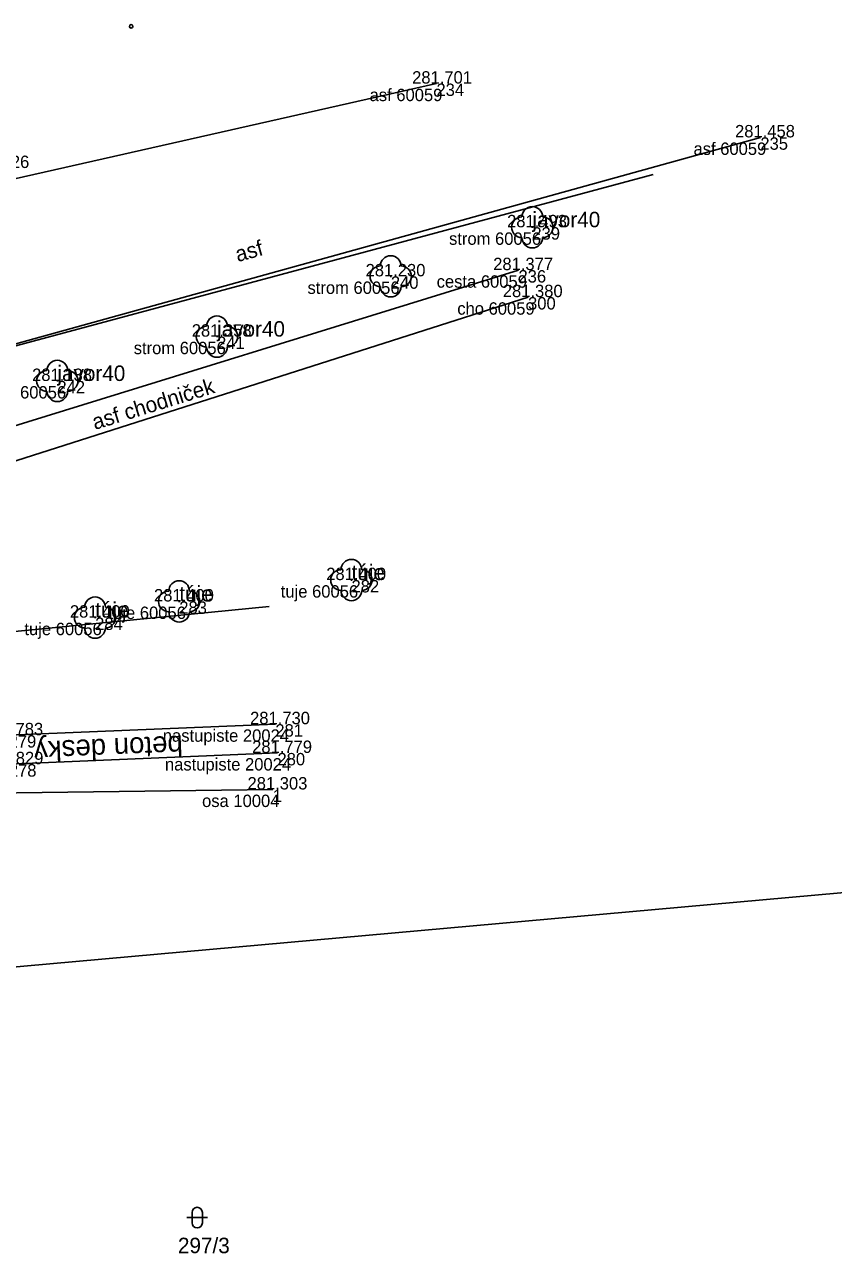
# Model space of a CAD drawing. Extents: x -728659 to -728362, y -1073110 to -1072943.
# Drawn here: x -728474.1 to -728435, y -1073066.8 to -1073007.2 of the extents above; entities that cross this region are included whole.
import ezdxf

# ---------------------------------------------------------------- set-up
doc = ezdxf.new("R2010")
doc.units = 0
for name, color, linetype in [('Vrstva 1', 7, 'Continuous'), ('Vrstva 14', 7, 'Continuous'), ('Vrstva 50', 7, 'Continuous'), ('Vrstva 51', 7, 'Continuous'), ('Vrstva 53', 7, 'Continuous'), ('Vrstva 55', 7, 'Continuous'), ('Vrstva 57', 7, 'Continuous'), ('Vrstva 58', 7, 'Continuous'), ('Vrstva 59', 7, 'Continuous'), ('Vrstva 60', 7, 'Continuous'), ('Vrstva 61', 7, 'Continuous'), ('Vrstva 62', 7, 'Continuous'), ('Vrstva 63', 7, 'Continuous')]:
    doc.layers.add(name, color=color, linetype=linetype)

msp = doc.modelspace()

# ---------------------------------------------------------------- linework, layer by layer
at = {"layer": 'Vrstva 1'}
msp.add_lwpolyline([(-728462.112, -1073044.292), (-728486.957, -1073044.611), (-728498.776, -1073043.699), (-728511.695, -1073041.857), (-728514.393, -1073041.361), (-728535.912, -1073035.983), (-728560.369, -1073026.548)], dxfattribs=at)
at = {"layer": 'Vrstva 14'}
msp.add_lwpolyline([(-728461.988, -1073041.13), (-728474.913, -1073041.665), (-728486.835, -1073041.479), (-728486.937, -1073042.858), (-728474.902, -1073043.068), (-728461.886, -1073042.523)], dxfattribs=at)
at = {"layer": 'Vrstva 50'}
for p, q in [((-728449.571, -1073017.062), (-728449.5, -1073017.062)), ((-728456.429, -1073019.439), (-728456.358, -1073019.439)), ((-728464.848, -1073022.358), (-728464.777, -1073022.358)), ((-728472.584, -1073024.506), (-728472.513, -1073024.506)), ((-728458.334, -1073034.149), (-728458.264, -1073034.149)), ((-728466.679, -1073035.184), (-728466.608, -1073035.184)), ((-728470.755, -1073035.967), (-728470.684, -1073035.967))]:
    msp.add_line(p, q, dxfattribs=at)
for centre, start, end in [((-728449.542, -1073016.561), 0, 180), ((-728450.042, -1073017.061), 90, 270), ((-728449.042, -1073017.061), 270, 90), ((-728449.542, -1073017.561), 180, 0), ((-728456.399, -1073018.938), 0, 180), ((-728456.899, -1073019.438), 90, 270), ((-728455.899, -1073019.438), 270, 90), ((-728456.399, -1073019.938), 180, 0), ((-728465.319, -1073022.357), 90, 270), ((-728464.819, -1073021.857), 0, 180), ((-728464.319, -1073022.357), 270, 90), ((-728464.819, -1073022.857), 180, 0), ((-728472.554, -1073024.005), 0, 180), ((-728473.054, -1073024.505), 90, 270), ((-728472.054, -1073024.505), 270, 90), ((-728472.554, -1073025.005), 180, 0), ((-728458.304, -1073033.648), 0, 180), ((-728458.804, -1073034.148), 90, 270), ((-728457.804, -1073034.148), 270, 90), ((-728466.65, -1073034.683), 0, 180), ((-728470.726, -1073035.466), 0, 180), ((-728467.15, -1073035.183), 90, 270), ((-728466.15, -1073035.183), 270, 90), ((-728458.304, -1073034.648), 180, 0), ((-728471.226, -1073035.966), 90, 270), ((-728470.226, -1073035.966), 270, 90), ((-728466.65, -1073035.683), 180, 0), ((-728470.726, -1073036.466), 180, 0)]:
    msp.add_arc(centre, 0.5, start, end, dxfattribs=at)
at = {"layer": 'Vrstva 51'}
for points in [[(-728494.628, -1073019.466), (-728481.269, -1073016.431), (-728476.07, -1073015.036), (-728454.183, -1073010.103)], [(-728491.401, -1073027.273), (-728490.555, -1073027.131), (-728438.49, -1073012.708)], [(-728491.25, -1073027.888), (-728489.777, -1073030.86), (-728476.655, -1073027.306), (-728450.209, -1073019.139)], [(-728449.745, -1073020.446), (-728480.35, -1073030.208), (-728490.255, -1073033.191), (-728496.482, -1073035.776)]]:
    msp.add_lwpolyline(points, dxfattribs=at)
at = {"layer": 'Vrstva 53'}
msp.add_lwpolyline([(-728443.68, -1073014.51), (-728493.68, -1073027.94), (-728497.54, -1073030.15), (-728499.78, -1073032.61), (-728501.19, -1073037.94), (-728503.24, -1073052.34), (-728496.81, -1073052.21), (-728491.97, -1073053.44), (-728477.97, -1073053.19), (-728434.587, -1073049.291), (-728361.73, -1073039.5)], dxfattribs=at)
at = {"layer": 'Vrstva 55'}
msp.add_lwpolyline([(-728462.29, -1073035.43), (-728488.6, -1073038.02), (-728488.39, -1073034.38), (-728493.51, -1073034.35), (-728493.84, -1073039.37), (-728501.19, -1073037.94)], dxfattribs=at)
at = {"layer": 'Vrstva 58'}
for p, q in [((-728466.277, -1073065.028), (-728465.277, -1073065.028)), ((-728466.027, -1073064.778), (-728466.027, -1073065.278)), ((-728465.527, -1073064.778), (-728465.527, -1073065.278))]:
    msp.add_line(p, q, dxfattribs=at)
for centre, start, end in [((-728465.777, -1073064.778), 0, 180), ((-728465.777, -1073065.278), 180, 0)]:
    msp.add_arc(centre, 0.25, start, end, dxfattribs=at)
at = {"layer": 'Vrstva 59'}
msp.add_circle((-728468.974, -1073007.333), 0.0873, dxfattribs=at)
at = {"layer": 'Vrstva 60'}
for p, q in [((-728454.183, -1073010.103), (-728454.183, -1073010.103)), ((-728438.49, -1073012.708), (-728438.49, -1073012.708)), ((-728449.536, -1073017.062), (-728449.536, -1073017.062)), ((-728456.393, -1073019.439), (-728456.393, -1073019.439)), ((-728450.209, -1073019.139), (-728450.209, -1073019.139)), ((-728449.745, -1073020.446), (-728449.745, -1073020.446)), ((-728464.813, -1073022.358), (-728464.813, -1073022.358)), ((-728472.548, -1073024.506), (-728472.548, -1073024.506)), ((-728458.299, -1073034.149), (-728458.299, -1073034.149)), ((-728466.644, -1073035.184), (-728466.644, -1073035.184)), ((-728470.72, -1073035.967), (-728470.72, -1073035.967)), ((-728461.988, -1073041.13), (-728461.988, -1073041.13)), ((-728461.886, -1073042.523), (-728461.886, -1073042.523)), ((-728462.112, -1073044.292), (-728462.112, -1073044.292))]:
    msp.add_line(p, q, dxfattribs=at)

# ---------------------------------------------------------------- texts
at = {"layer": 'Vrstva 14'}
msp.add_text('beton desky', height=1, rotation=182.37027, dxfattribs=at).set_placement((-728466.491, -1073041.672))
at = {"layer": 'Vrstva 51'}
for s, rotation, p in [('asf', 15.48375, (-728463.812, -1073018.752)), ('asf chodniček', 17.16163, (-728470.731, -1073026.881))]:
    msp.add_text(s, height=0.75, rotation=rotation, dxfattribs=at).set_placement(p)
at = {"layer": 'Vrstva 57'}
msp.add_text('297/3', height=0.75, dxfattribs=at).set_placement((-728466.708, -1073066.751))
at = {"layer": 'Vrstva 60'}
for s, p in [('234', (-728454.183, -1073010.703)), ('235', (-728438.49, -1073013.308)), ('239', (-728449.536, -1073017.662)), ('240', (-728456.393, -1073020.039)), ('236', (-728450.209, -1073019.739)), ('300', (-728449.745, -1073021.046)), ('241', (-728464.813, -1073022.958)), ('242', (-728472.548, -1073025.106)), ('282', (-728458.299, -1073034.749)), ('283', (-728466.644, -1073035.784)), ('284', (-728470.72, -1073036.567)), ('281', (-728461.988, -1073041.73)), ('279', (-728474.913, -1073042.265)), ('280', (-728461.886, -1073043.123)), ('278', (-728474.902, -1073043.668)), ('1', (-728462.112, -1073044.892))]:
    msp.add_text(s, height=0.6, dxfattribs=at).set_placement(p)
at = {"layer": 'Vrstva 61'}
for s, p in [('281.701', (-728455.362, -1073010.103)), ('281.458', (-728439.717, -1073012.708)), ('281.326', (-728476.812, -1073014.192)), ('281.493', (-728450.762, -1073017.062)), ('281.230', (-728457.618, -1073019.439)), ('281.377', (-728451.435, -1073019.139)), ('281.380', (-728450.97, -1073020.446)), ('281.358', (-728466.04, -1073022.358)), ('281.138', (-728473.775, -1073024.506)), ('281.400', (-728459.524, -1073034.149)), ('281.400', (-728467.869, -1073035.184)), ('281.400', (-728471.945, -1073035.967)), ('281.730', (-728463.213, -1073041.13)), ('281.783', (-728476.139, -1073041.665)), ('281.779', (-728463.113, -1073042.523)), ('281.829', (-728476.129, -1073043.068)), ('281.303', (-728463.338, -1073044.292))]:
    msp.add_text(s, height=0.6, dxfattribs=at).set_placement(p)
at = {"layer": 'Vrstva 62'}
for s, p in [('asf 60059', (-728457.422, -1073010.953)), ('asf 60059', (-728441.729, -1073013.558)), ('strom 60056', (-728453.575, -1073017.912)), ('cesta 60059', (-728454.174, -1073019.989)), ('strom 60056', (-728460.432, -1073020.289)), ('cho 60059', (-728453.175, -1073021.296)), ('strom 60056', (-728468.852, -1073023.208)), ('strom 60056', (-728476.587, -1073025.356)), ('tuje 60056', (-728461.727, -1073034.999)), ('tuje 60056', (-728470.072, -1073036.034)), ('tuje 60056', (-728474.148, -1073036.817)), ('nastupiste 20024', (-728467.441, -1073041.98)), ('nastupiste 20024', (-728467.339, -1073043.373)), ('osa 10004', (-728465.539, -1073045.142))]:
    msp.add_text(s, height=0.6, dxfattribs=at).set_placement(p)
at = {"layer": 'Vrstva 63'}
for s, p in [('javor40', (-728449.536, -1073017.062)), ('javor40', (-728464.813, -1073022.358)), ('javor40', (-728472.548, -1073024.506)), ('túje', (-728458.299, -1073034.149)), ('túje', (-728466.644, -1073035.184)), ('túje', (-728470.72, -1073035.967))]:
    msp.add_text(s, height=0.75, dxfattribs=at).set_placement(p)

doc.saveas('drawing.dxf')
